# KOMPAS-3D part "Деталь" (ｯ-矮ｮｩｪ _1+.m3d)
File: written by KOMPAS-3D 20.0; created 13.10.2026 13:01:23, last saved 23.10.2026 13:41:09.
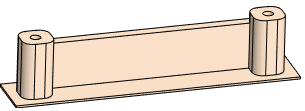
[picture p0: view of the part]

Document properties: Полное имя файла: D:\RicWork\Project-EPS32\box_compas\stl 3d printer\п-стойка_1+.m3d

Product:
- Part/product: Деталь
    Масса: 0.0122773
  - Body: Тело 1
      Масса: 0.00935935

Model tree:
1. Эскиз:1
2. Элемент выдавливания:1
     Расстояние 1 = 11
3. Эскиз:2  (with: Элемент выдавливания:1)
4. Элемент выдавливания:2
     Расстояние 2 = 11
5. Массив по сетке:1  (with: Элемент выдавливания:2, Эскиз:2)  (2 pattern instances)
     Шаг 1 = 10; Угол раствора = -90; Шаг 2 = 44.2
6. Эскиз:3  (with: Элемент выдавливания:1)
7. Элемент выдавливания:3
     Расстояние 2 = 2
8. Эскиз:4  (with: Элемент выдавливания:1)
9. Элемент выдавливания:4
     Расстояние 2 = 2
10. Скругление:1  (with: Элемент выдавливания:1)
     Радиус = 2
11. Элемент выдавливания:5  (with: Элемент выдавливания:3)
     Расстояние 1 = 2
12. Эскиз:5  (with: Элемент выдавливания:1)
13. Элемент выдавливания:6
     Расстояние 1 = 0.4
